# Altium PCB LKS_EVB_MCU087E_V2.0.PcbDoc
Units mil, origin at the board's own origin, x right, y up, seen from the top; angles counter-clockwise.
Board outline 1880 x 1270 mil, 2 copper layers (Top Layer, Bottom Layer); 32 components, 28 nets, 108 pads, 52 vias.
Unrouted connection lines stored in the file: 3.
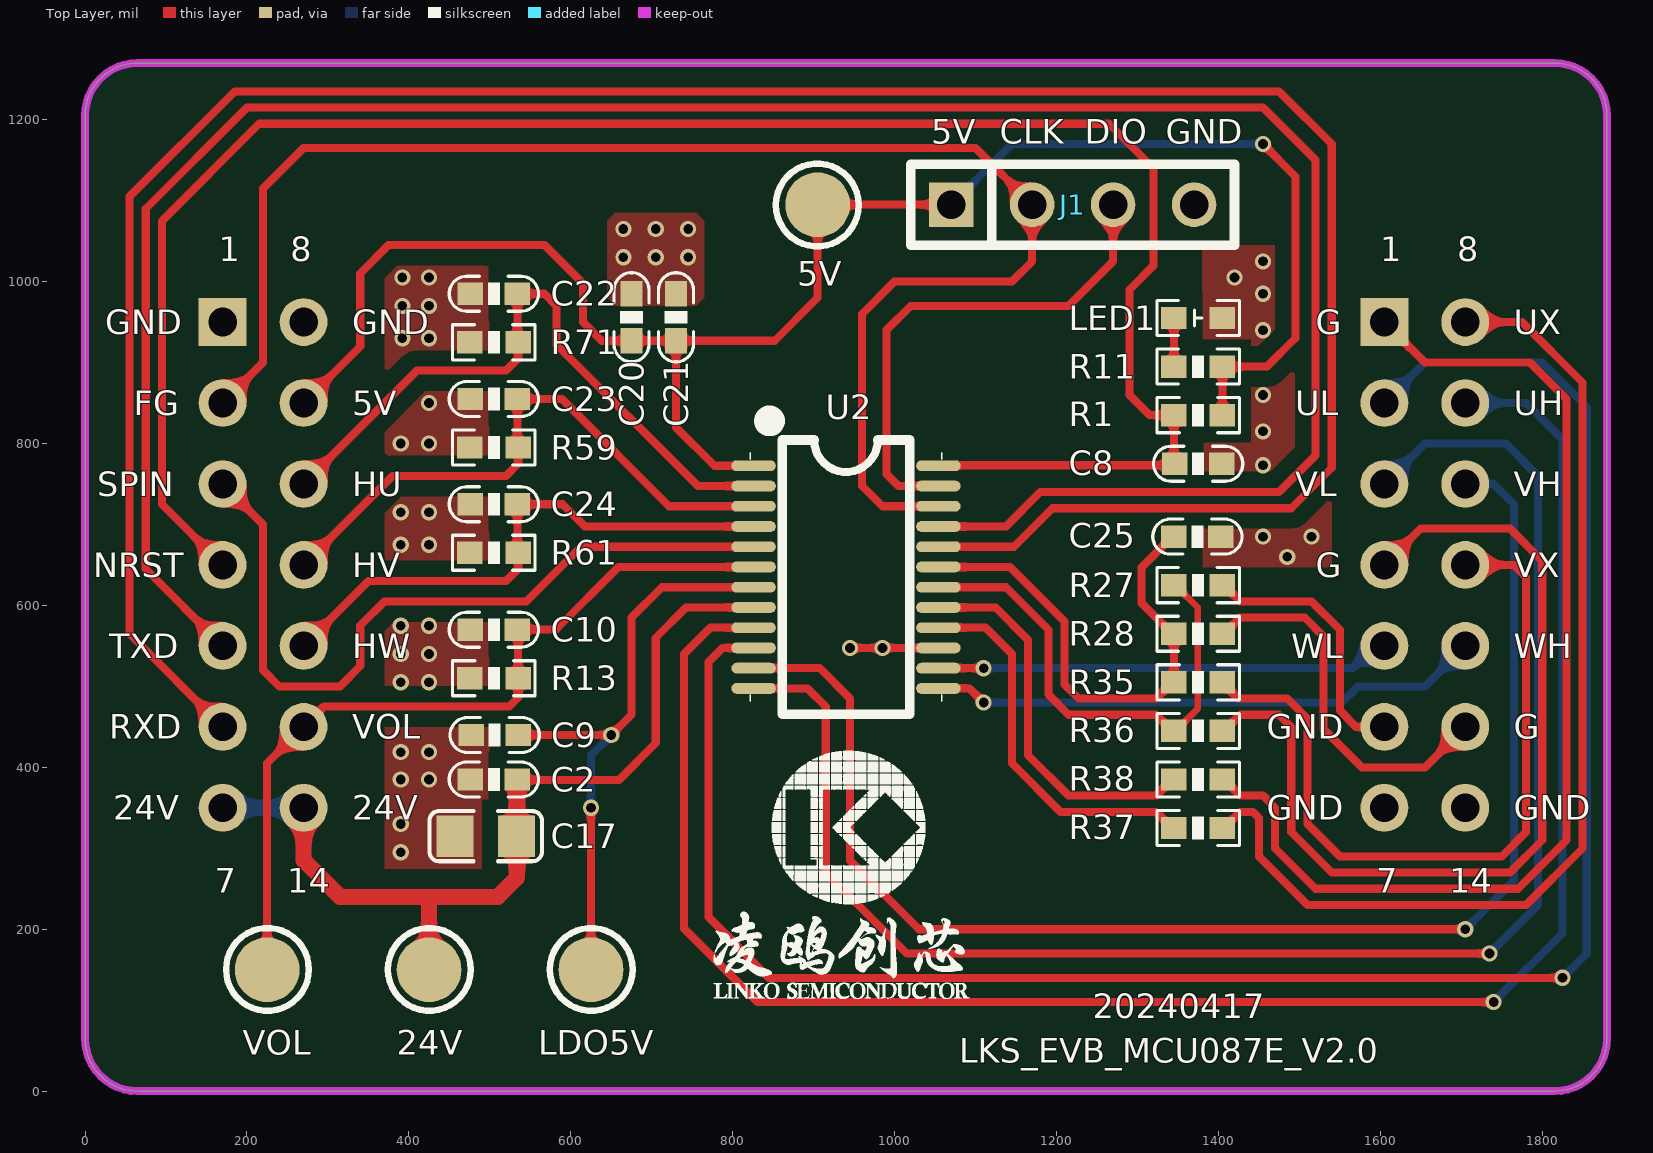
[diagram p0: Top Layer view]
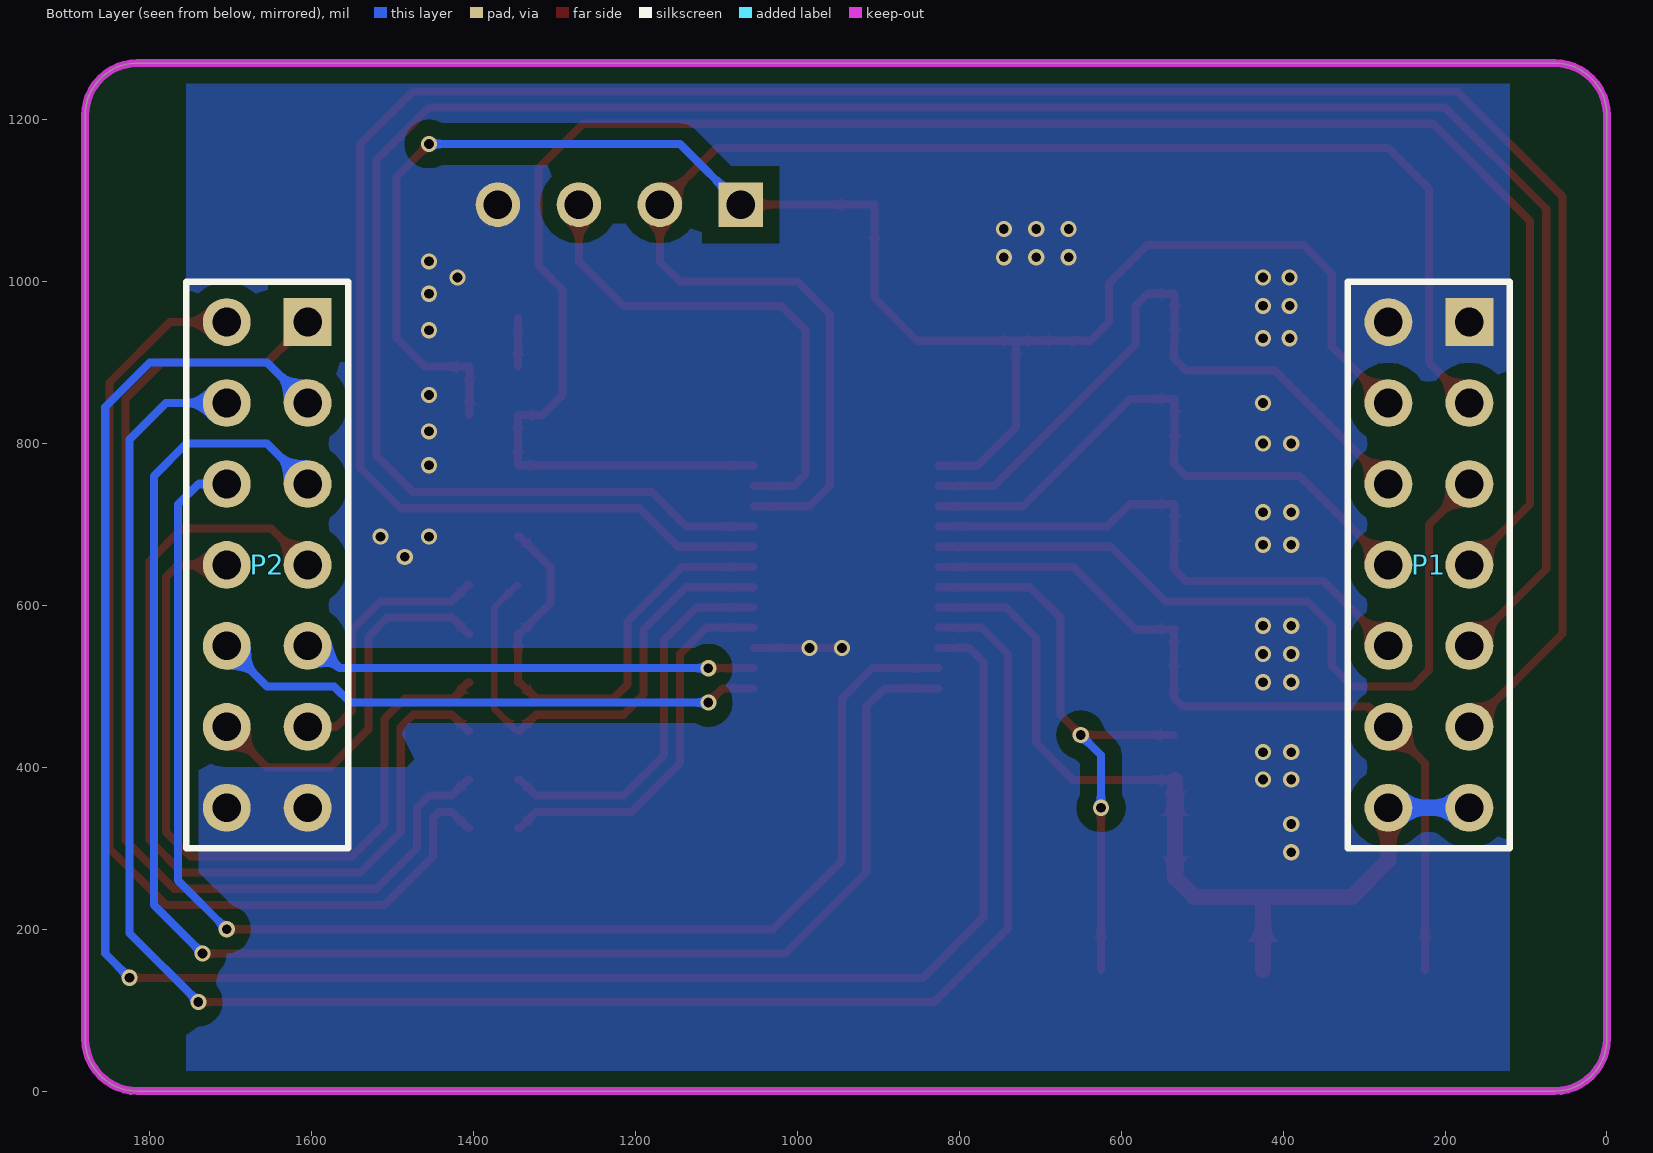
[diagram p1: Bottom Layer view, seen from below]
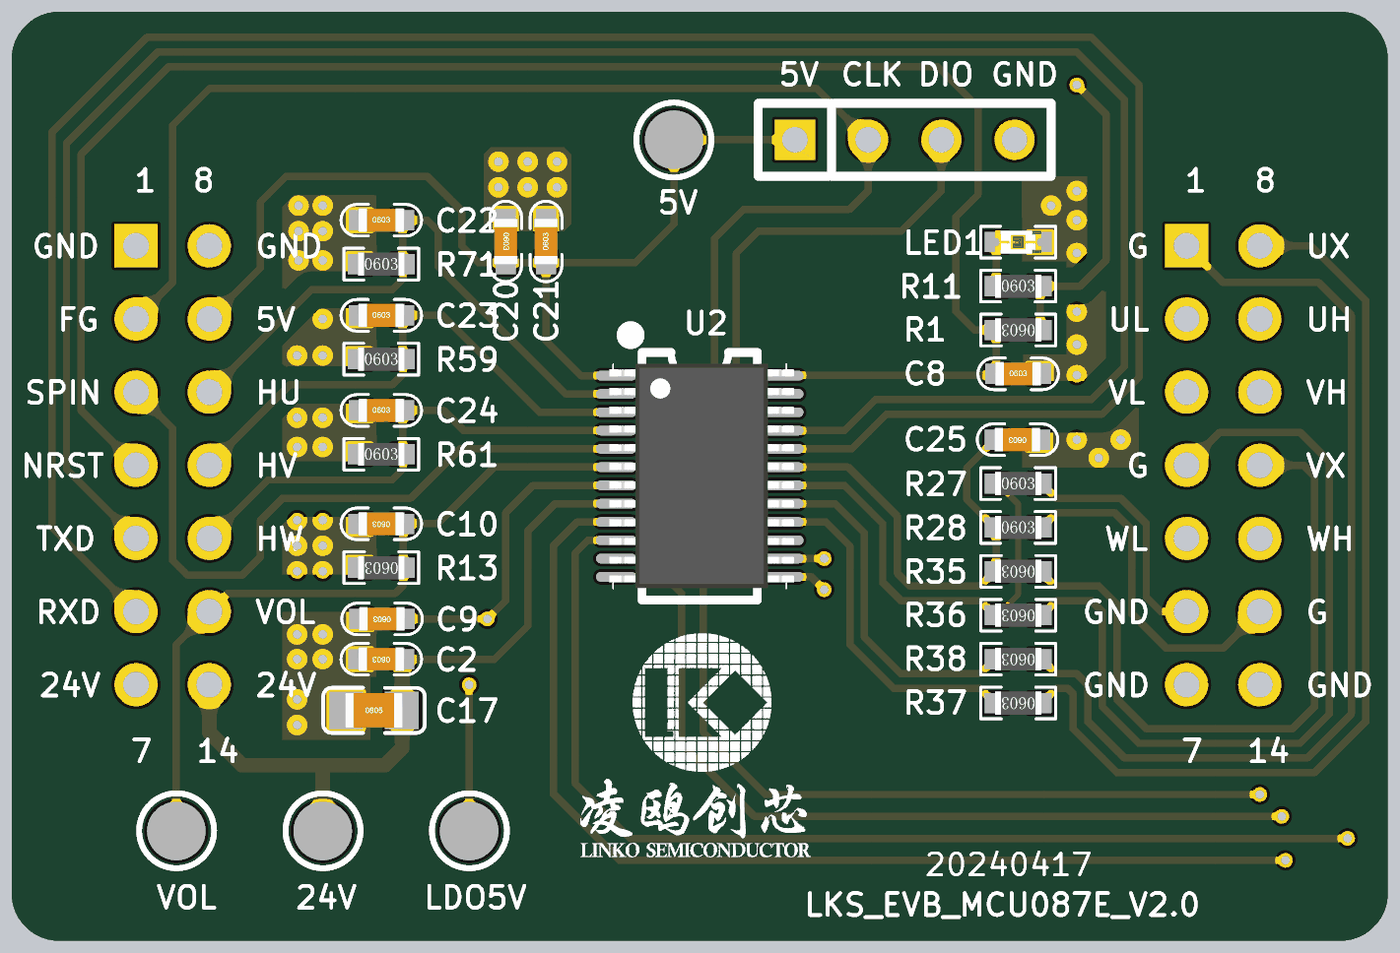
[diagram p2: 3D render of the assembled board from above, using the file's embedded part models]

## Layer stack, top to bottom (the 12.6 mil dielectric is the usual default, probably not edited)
Top Solder: solder mask 0.4, Solder Resist, Dk 3.5
Top Layer: signal copper 1.4
Dielectric1: dielectric 12.6, FR-4, Dk 4.8
Bottom Layer: signal copper 1.4
Bottom Solder: solder mask 0.4, Solder Resist, Dk 3.5

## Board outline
0,65 0,1205 cw(c65,1205) 65,1270 1815,1270 cw(c1815,1205) 1880,1205 1880,65 cw(c1815,65) 1815,0 65,0 cw(c65,65)

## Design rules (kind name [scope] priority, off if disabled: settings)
Clearance Clearance_1 [INPolygon] p1: gap=20 ignorepadtopadclearanceinfootprint=FALSE except(0: Arc-Hole Track-Hole SMDPad-Hole THPad-Hole Via-Hole Fill-Hole Poly-Hole Region-Hole Text-Hole)
Clearance [All] p2: gap=10 ignorepadtopadclearanceinfootprint=FALSE except(0: Arc-Hole Track-Hole SMDPad-Hole THPad-Hole Via-Hole Fill-Hole Poly-Hole Region-Hole Text-Hole)
ComponentClearance [All] p1: gap=0 collisioncheckmode=3 verticalgap=0 showdistances=FALSE
FabricationTestpoint [(IsPad And (OnTopLayer Or OnBottomLayer))] p1: side=3 testpointundercomponent=TRUE minsize=40 maxsize=100 preferedsize=60 minholesize=0 maxholesize=40 preferedholesize=32 testpointgrid=1 allowsidetop=TRUE allowsidebottom=TRUE usegrid=TRUE gridtolerance=0.01
PolygonConnect [All] p1: connectstyle=Direct reliefconductorwidth=20 reliefentries=4 polygonreliefangle="90 Angle" airgapwidth=10
RoutingVias [All] p1: holewidth=12 width=20 viastyle="Through Hole" minholewidth=0 minwidth=10 maxholewidth=30 maxwidth=50
SilkToSolderMaskClearance SilkscreenOverComponentPads [IsPad] p1: minsilkscreentomaskgap=10 clearancetoexposedcopper=TRUE
SolderMaskExpansion [All] p1: expansion=4 istentingtop=FALSE
Width [All] p1: maxlimit=300 minlimit=1 preferedwidth=10
27 further rules are at their usual default settings.

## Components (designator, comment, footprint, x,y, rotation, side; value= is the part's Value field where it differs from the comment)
5V "TestP" TP-80 904.61,1094.61 r270 top
24V "TestP" TP-80 425.39,150.39 r90 top
C2 "100nF/50V" 0603C 505,385 r180 top
C8 "100nF/50V" 0603C 1375,775 r0 top
C9 "1uF/10V" 0603C 506,440 r180 top
C10 "100nF/50V" 0603C 505,570 r180 top
C17 "10uF/50V" 0805C 495,315 r0 top
C20 "10uF/16V" 0603C 675,956 r270 top
C21 "100nF/50V" 0603C 730,955.95 r90 top
C22 "1nF/50V" 0603C 505,985 r0 top
C23 "1nF/50V" 0603C 505,855 r0 top
C24 "1nF/50V" 0603C 505,725 r0 top
C25 "100pF/50V" 0603C 1374.06,685 r180 top
J1 "SWD" SIP4-2.5 1220,1095 r0 top
LDO5V "TestP" TP-80 625.39,150.39 r90 top
LED1 "" "LED 0603R" 1375,955 r0 top
P1 "Header 7X2A" HDR2X7_CEN 170,950 r270 bottom locked
P2 "Header 7X2A" HDR2X7_CEN 1605,950 r270 bottom locked
R1 "20K" 0603R 1375,835 r180 top
R11 "3.3K" 0603R 1375,895 r0 top
R13 "3.3K" 0603R 505,510 r180 top
R27 "1K" 0603R 1375,625 r0 top
R28 "1K" 0603R 1375,565 r0 top
R35 "1K" 0603R 1375,505 r180 top
R36 "1K" 0603R 1375,445 r180 top
R37 "1K" 0603R 1375,325 r180 top
R38 "1K" 0603R 1375,385 r180 top
R59 "3.3K" 0603R 505,795 r0 top
R61 "3.3K" 0603R 505,665 r0 top
R71 "3.3K" 0603R 505,925 r0 top
U2 "LKS32MC087EM6S8" SSOP24 940,635 r270 top locked
VOL "TestP" TP-80 225.39,150.39 r90 top

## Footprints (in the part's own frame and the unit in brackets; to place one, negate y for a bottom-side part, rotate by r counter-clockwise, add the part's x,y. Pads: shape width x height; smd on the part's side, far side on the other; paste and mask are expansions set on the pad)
0603C [mm] "电容"
  rect 0.8x0.7 smd: 1(-0.737,0) 2(0.738,0)
  silkscreen extent -1.4,-0.55 1.4,0.55, body extent -0.8,-0.41 0.8,0.41, height 0.81
0603R [mm] "电阻"
  rect 0.8x0.7 smd: 1(-0.762,0) 2(0.762,0)
  silkscreen extent -1.3,-0.55 1.3,0.55, body extent -0.8,-0.4 0.8,0.4, height 0.45
0805C [mil] "电容"
  rect 46x51.18 smd: 1(-38,0) 2(38,0)
  silkscreen extent -69,-31 70,31, body extent -39,-24 39,24, height 20
HDR2X7_CEN [mm] "Connector; Header; 7x2 Position"
  rect 1.5x1.5 hole 0.9: 1(0,0)
  round 1.5 hole 0.9: 2(2.54,0) 3(5.08,0) 4(7.62,0) 5(10.16,0) 6(12.7,0) 7(15.24,0) 8(0,-2.54) 9(2.54,-2.54) 10(5.08,-2.54) 11(7.62,-2.54) 12(10.16,-2.54) 13(12.7,-2.54) 14(15.24,-2.54)
  silkscreen extent -1.27,-3.81 16.51,1.27
"LED 0603R" [mm] "LED"
  rect 0.8x0.7 smd: 1(-0.762,0) 2(0.762,0)
  silkscreen extent -1.3,-0.55 1.3,0.55, body extent -0.8,-0.4 0.8,0.4, height 0.47
SIP4-2.5 [mil]
  rect 55x55 hole 35: 1(-150,0)
  round 55 hole 35: 2(-50,0) 3(50,0) 4(150,0)
  silkscreen extent -200,-50 200,50
SSOP24 [mm] "LINKO-087"
  oval 0.34x1.4 smd: 1(-3.492,-2.9) 2(-2.857,-2.9) 3(-2.222,-2.9) 4(-1.587,-2.9) 5(-0.952,-2.9) 6(-0.317,-2.9) 7(0.318,-2.9) 8(0.953,-2.9) 9(1.588,-2.9) 10(2.223,-2.9) 11(2.858,-2.9) 12(3.493,-2.9) 13(3.492,2.9) 14(2.857,2.9) 15(2.222,2.9) 16(1.587,2.9) 17(0.952,2.9) 18(0.317,2.9) 19(-0.318,2.9) 20(-0.953,2.9) 21(-1.588,2.9) 22(-2.223,2.9) 23(-2.858,2.9) 24(-3.493,2.9)
  silkscreen extent -5,-3 4.3,3, body extent -3.91,-3.14 3.89,3.27, height 1.03
TP-80 [mil]
  round 80 smd: 1(-0.39,0.39)
  silkscreen extent -51,-51 51,51

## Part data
C2 C10 C17 C20 C21: library part CAP, "Capacitor"
C8 C9 C22 C23 C24 C25: library part C, "Capacitor"
J1: library part "Header 4", "Header, 4-Pin"
LED1: library part LED2, "Typical RED, GREEN, YELLOW, AMBER GaAs LED"
P1 P2: "Header, 7-Pin, Dual row"
R1 R27 R28 R35 R36 R37 R38: library part RES2-1
R11 R13: library part Res2, "Resistor"
R59 R61 R71: library part RES/1
U2: "芯片"

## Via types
v1: diameter 20, hole 12, Top Layer to Bottom Layer, 52 vias

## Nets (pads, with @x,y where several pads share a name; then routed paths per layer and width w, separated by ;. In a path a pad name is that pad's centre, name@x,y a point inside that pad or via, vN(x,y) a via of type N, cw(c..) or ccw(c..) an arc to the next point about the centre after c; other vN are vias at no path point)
5V: 5V.1 C20.2 C21.1 J1.1 P1.9 R1.1 R11.2 U2.1 | length 2206.8
  Top Layer w10: P1.9 340,920 340,1010 375,1045 567.5,1045 615,997.5 615,950 638.05,926.95 C20.2 C21.1 ; U2.1 777.5,772.5 730,820 C21.1 ; J1.1 5V.1 905,980 851.94,926.95 C21.1 ; R1.1 R11.2 1460,895 1495,930 1495,1130 v1(1455,1170)
  Bottom Layer w10: J1.1 1145,1170 v1(1455,1170)
24V: 24V.1 C2.1 C17.2 P1.7 P1.14 U2.8 | length 1125.6
  Top Layer w10: C2.1@533.5,384.5 659.5,384.5 705,430 705,560 742.5,597.5 U2.8
  Top Layer w20: P1.14 270,285 315,240 427.5,240 ; 24V.1 425,237.5 427.5,240 ; C2.1@533.5,384.5 533.5,314.97 533.5,263.5 510,240 427.5,240
  Bottom Layer w20: P1.7 P1.14
FG: J1.2 P1.2 U2.22 | length 1909.4
  Top Layer w10: P1.2 220,900 220,1115 270,1165 1100,1165 J1.2 1170,1025 1145,1000 1000,1000 960,960 960,747.5 985,722.5 U2.22
G: P2.1 P2.4 P2.13 R28.2 R36.1 R38.1 | length 2969.1
  Top Layer w10: R38.1 1406.97,385 1426.97,365 1455,365 1470,350 1470,300 1520,250 1770,250 1830,310 1830,855 1785,900 1655,900 P2.1 ; R36.1 1406.97,445 1426.97,465 1475,465 1490,450 1490,320 1540,270 1760,270 1800,310 1800,655 1760,695 1650,695 P2.4 ; R28.2 1406.97,565 1426.97,585 1506.72,585 1530,561.72 1530,447.17 1577.17,400 1655,400 P2.13
GND: C2.2 C8.2 C9.2 C10.2 C17.1 C20.1 C21.2 C22.1 C23.1 C24.1 C25.1 J1.4 LED1.2 P1.1 P1.8 P2.6 P2.7 P2.14 R13.2 R27.2 R59.1 R61.1 R71.1 U2.15 | length 440.2
  Top Layer w10: v1(945,547.5) U2.15 ; R27.2 1406.97,625 1426.97,605 1515,605 1550,570 1550,470 1570,450 P2.6
  other v1: 390,295 390,330 390,384.97 425,385 390,418.78 425,418.78 390,505 425,505 390,540 425,540 985,547.5 390,575 425,575 1485,660 390,675 425,675 1455,685 1515,685 390,715 425,715 1455,773.15 390,800 425,800 1455,815 425,850 1455,860 391.98,930 425,930 1455,940 391.98,970 425,970 1455,985 391.98,1005 425,1005 1420,1005 1455,1025 665,1030 705,1030 745,1030 665,1065 705,1065 745,1065
HU&PU: C22.2 P1.10 R71.2 U2.2 | length 826.5
  Top Layer w10: P1.10 410,890 520,890 535,905 R71.2 ; R71.2@534.05,925.95 C22.2 567.5,985 582.5,970 582.5,922.07 757.07,747.5 U2.2
HV&PV: C23.2 P1.11 R59.2 U2.3 | length 742.4
  Top Layer w10: P1.11 380,760 520,760 535,775 R59.2 ; R59.2@534.05,796.02 C23.2 589.03,855 721.53,722.5 U2.3
HW&PW: C24.2 P1.12 R61.2 U2.4 | length 686.5
  Top Layer w10: P1.12 350,630 520,630 535,645 R61.2 ; R61.2@534.05,666.02 C24.2 590,725 617.5,697.5 U2.4
LDO5V: C9.1 LDO5V.1 U2.7 | length 737.1
  Top Layer w10: C9.1 v1(650,440) 675,465 675,585 712.5,622.5 U2.7 ; LDO5V.1 v1(625,350)
  Bottom Layer w10: v1(625,350) 625,415 v1(650,440)
NetLED1_1: LED1.1 R11.1 | length 60
  Top Layer w10: R11.1 LED1.1
NRST: C8.1 P1.4 R1.2 U2.24 | length 2463.8
  Top Layer w10: P1.4 95,725 95,1075 215,1195 1265,1195 1320,1140 1320,1020 1290,990 1290,860 1315,835 R1.2 1345,774 1344.15,773.15 1054.82,773.15 U2.24
OPA2_IN: R38.2 U2.17 | length 478.9
  Top Layer w10: U2.17 1125,597.5 1165,557.5 1165,415 1215,365 1323.03,365 1343.03,385 R38.2
OPA2_IP: R37.2 U2.16 | length 472.4
  Top Layer w10: U2.16 1112.5,572.5 1145,540 1145,405 1205,345 1323.03,345 1343.03,325 R37.2
OPA3_IN: R27.1 R36.2 U2.18 | length 618.2
  Top Layer w8: R36.2@1343.03,445 R36.2 1346.97,445 1374.75,472.78 1374.75,597.22 1346.97,625 R27.1
  Top Layer w10: U2.18 1137.5,622.5 1190,570 1190,490 1215,465 1323.03,465 R36.2@1343.03,445
OPA3_IP: C25.2 R28.1 R35.2 U2.19 | length 625.3
  Top Layer w10: U2.19 1142.5,647.5 1210,580 1210,502.5 1227.5,485 1323.03,485 R35.2@1343.03,505 ; R35.2 R28.1 1343.03,565 1305,603.03 1305,646.97 1343.03,685 C25.2
RXD: P1.6 U2.20 | length 3194.6
  Top Layer w10: P1.6 55,565 55,1105 185,1235 1475,1235 1540,1170 1540,770 1490,720 1195,720 1147.5,672.5 U2.20
SPIN: P1.3 U2.5 | length 965.6
  Top Layer w10: P1.3 220,700 220,520 240,500 315,500 340,525 340,575 370,605 545,605 612.5,672.5 U2.5
SWDIO: J1.3 U2.23 | length 633.1
  Top Layer w10: U2.23 1005,747.5 990,762.5 990,940 1020,970 1215,970 1270,1025 J1.3
TXD: P1.5 U2.21 | length 2970.1
  Top Layer w10: P1.5 75,645 75,1090 200,1215 1455,1215 1520,1150 1520,785 1475,740 1180,740 1137.5,697.5 U2.21
UH: P2.9 U2.9 | length 2344.9
  Top Layer w10: U2.9 772.5,572.5 740,540 740,200.81 830.81,110 v1(1740,110)
  Bottom Layer w10: P2.9 1780,850 1825,805 1825,195 v1(1740,110)
UL: P2.2 U2.10 | length 2475.1
  Top Layer w10: U2.10 787.5,547.5 770,530 770,215 845,140 v1(1825,140)
  Bottom Layer w10: P2.2 1655,900 1800,900 1855,845 1855,170 v1(1825,140)
UX: P2.8 R37.1 | length 1308.7
  Top Layer w10: R37.1 1406.97,325 1426.84,344.87 1442.56,344.87 1450,337.44 1450,290 1510,230 1780,230 1850,300 1850,875 1775,950 P2.8
VH: P2.10 U2.11 | length 1750.1
  Top Layer w10: U2.11 907.5,522.5 945,485 945,285 1030,200 v1(1705,200)
  Bottom Layer w10: v1(1705,200) 1765,260 1765,725 1740,750 P2.10
VL: P2.3 U2.12 | length 2007
  Top Layer w10: U2.12 892.5,497.5 915,475 915,270 1015,170 v1(1735,170)
  Bottom Layer w10: P2.3 1655,800 1755,800 1795,760 1795,230 v1(1735,170)
VOL: C10.1 P1.13 R13.1 U2.6 VOL.1 | length 1009.5
  Top Layer w10: VOL.1 225,405 P1.13 ; P1.13@272.97,450 P1.13 ; C10.1 533.5,570.5 582.15,570.5 659.15,647.5 U2.6 ; C10.1@535,569 R13.1 535,485.97 524.03,475 295,475 P1.13
VX: P2.11 R35.1 | length 950
  Top Layer w10: R35.1 1406.97,505 1415.75,496.22 1415.75,494.25 1425,485 1485,485 1510,460 1510,330 1550,290 1750,290 1780,320 1780,635 1765,650 P2.11
WH: P2.12 U2.13 | length 687.1
  Top Layer w10: U2.13 1092.5,497.5 v1(1110,480)
  Bottom Layer w10: v1(1110,480) 1552.42,480 1572.42,500 1655,500 P2.12
WL: P2.5 U2.14 | length 562.2
  Top Layer w10: U2.14 v1(1110,522.5)
  Bottom Layer w10: v1(1110,522.5) 1565.7,522.5 1593.2,550 P2.5

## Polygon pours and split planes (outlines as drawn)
GND on Top Layer "NONET_L-01_P-001" (solid, remove dead copper, pour order 5): 1540,1045 1540,635.11 1380.11,635.11 1380,635 1380,1045
GND on Top Layer "10" (solid, remove dead copper, pour order 8): 755,970 765,980 765,1075 755,1085 655,1085 645,1075 645,980 655,970
GND on Top Layer "NONET_L-01_P-001" (solid, remove dead copper, pour order 6): 370,275 505,275 505,1020 370,1020
GND on Bottom Layer "Bottom Layer-No Net" (solid, remove dead copper, pour order 4): 120,1270 120,0 1755,0 1755,1270

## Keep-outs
Keep-Out Layer:
  the board outline again, w10

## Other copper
Top Layer:
  pour cut-out: 1374.75,646.97 1629.84,646.97 1635,416.72 1441.39,416.72 1374.75,522.23
Bottom Layer:
  pour cut-out: 1515,493.28 1686.72,493.28 1705,475 1705,400.05 1482.77,400.05 1472.81,410

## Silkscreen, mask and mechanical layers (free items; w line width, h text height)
Top Overlay:
  drawing of 144 lines, arcs and shapes, not listed
  text "5V" at 1045,1170 h30
  text "CLK" at 1130,1170 h30
  text "DIO" at 1235,1170 h30
  text "GND" at 1335,1170 h30
  text "GND" at 25,935 h30
  text "GND" at 330,935 h30
  text "G" at 1520,935 h30
  text "UX" at 1765,935 h30
  text "FG" at 60,835 h30
  text "5V" at 330,835 h30
  text "UL" at 1495,835 h30
  text "UH" at 1765,835 h30
  text "SPIN" at 15,735 h30
  text "HU" at 330,735 h30
  text "VL" at 1495,735 h30
  text "VH" at 1765,735 h30
  text "NRST" at 10,635 h30
  text "HV" at 330,635 h30
  text "G" at 1520,635 h30
  text "VX" at 1765,635 h30
  text "TXD" at 30,535 h30
  text "HW" at 330,535 h30
  text "WL" at 1490,535 h30
  text "WH" at 1765,535 h30
  text "RXD" at 30,435 h30
  text "VOL" at 330,435 h30
  text "GND" at 1460,435 h30
  text "G" at 1765,435 h30
  text "24V" at 35,335 h30
  text "24V" at 330,335 h30
  text "GND" at 1460,335 h30
  text "GND" at 1765,335 h30
  text "20240417" at 1245,90 h30
  text "LKS_EVB_MCU087E_V2.0" at 1080,35 h30
Mechanical 1:
  the board outline again, w10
